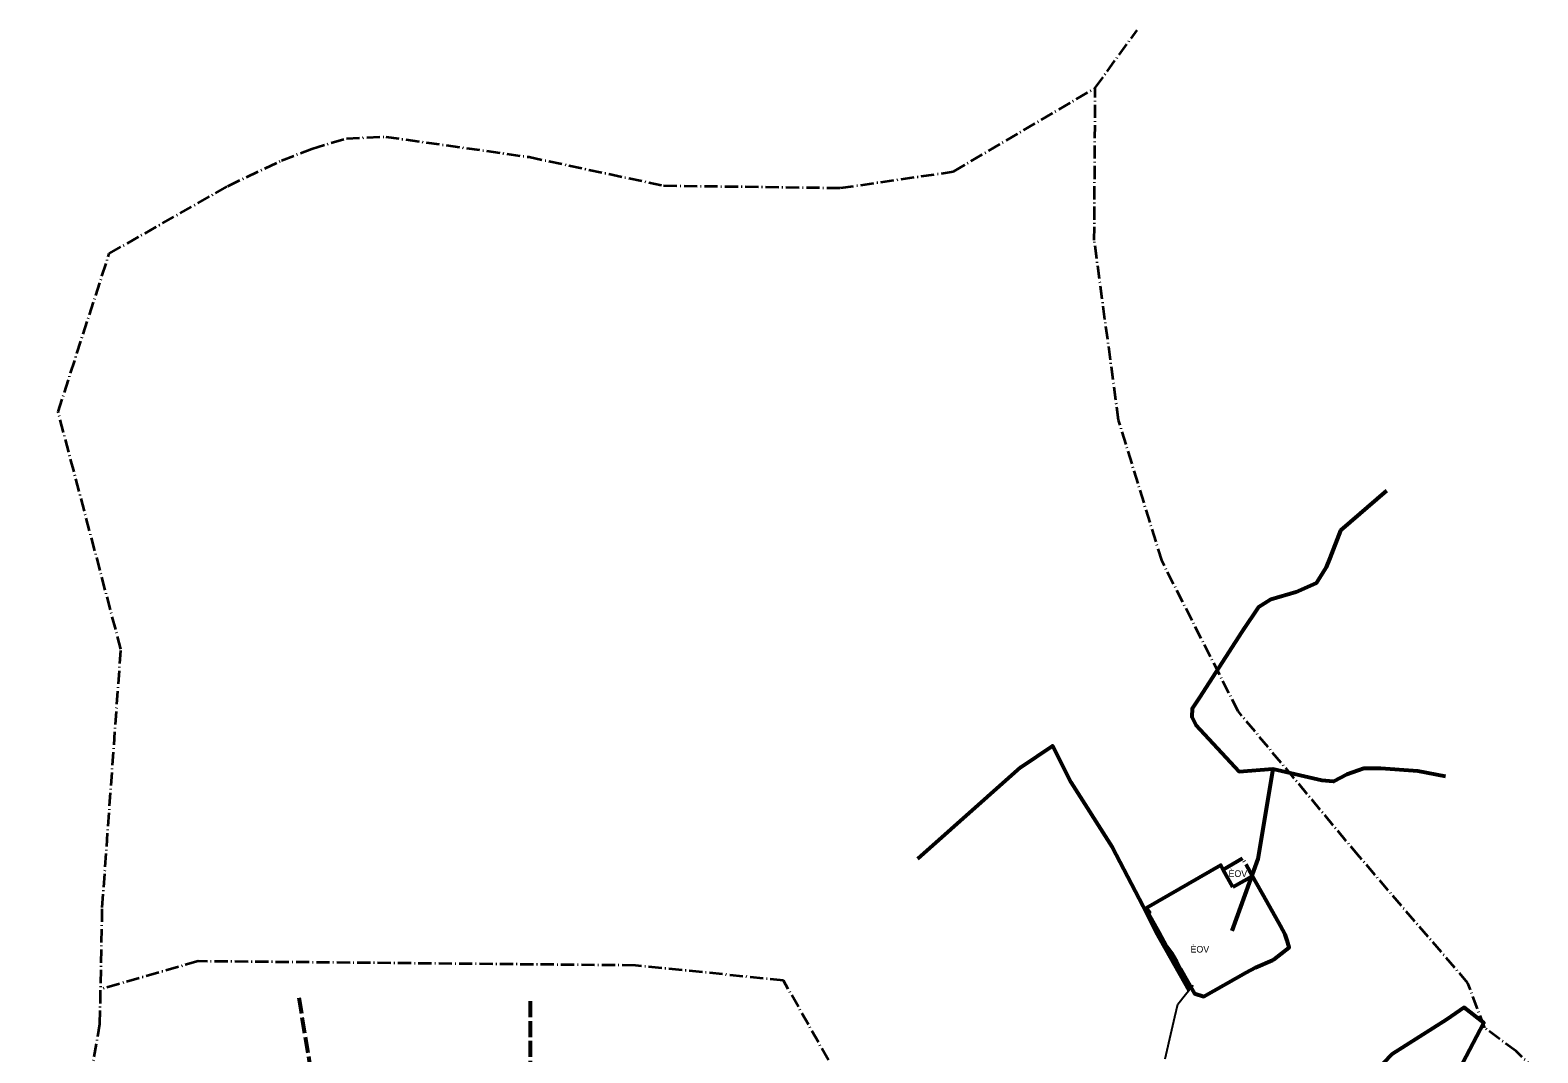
# Model space of a CAD drawing. Extents: x -650270 to -643402, y -1075206 to -1066724.
# Drawn here: x -647793 to -645515, y -1069326 to -1067780 of the extents above; entities that cross this region are included whole.
import ezdxf

# ---------------------------------------------------------------- set-up
doc = ezdxf.new("R2010")
doc.units = 0
doc.header["$LTSCALE"] = 4
doc.linetypes.add('DOT_DASHED', pattern=[7.7, 5, -1.2, 0.3, -1.2])
doc.linetypes.add('LONG_DASHED', pattern=[7.5, 6, -1.5])
for name, color, linetype, lineweight in [('16', 7, 'Continuous', 25), ('17', 7, 'DOT_DASHED', 35), ('21', 7, 'Continuous', 53), ('22', 7, 'DOT_DASHED', 53), ('43', 7, 'Continuous', 53), ('47', 7, 'Continuous', 40), ('48', 7, 'Continuous', 53), ('50', 7, 'Continuous', 53)]:
    doc.layers.add(name, color=color, linetype=linetype, lineweight=lineweight)

msp = doc.modelspace()

# ---------------------------------------------------------------- linework, layer by layer
at = {"layer": '16'}
msp.add_lwpolyline([(-646077.688, -1069335.173), (-646067.55, -1069291.329), (-646062.988, -1069271.856), (-646058.427, -1069252.383), (-646047.044, -1069237.982), (-646035.66, -1069223.58)], dxfattribs=at)
at = {"layer": '17'}
for points in [[(-648163.245, -1069677.659), (-647956.36, -1069616.266), (-647792.66, -1069528.568), (-647711.796, -1069423.024), (-647687.185, -1069282.298), (-647683.669, -1069106.39), (-647655.542, -1068715.876), (-647750.47, -1068357.024), (-647673.122, -1068117.79), (-647493.814, -1068015.764), (-647412.95, -1067977.064), (-647367.244, -1067959.473), (-647314.919, -1067943.73), (-647255.446, -1067941.26), (-647038.873, -1067971.862), (-646835.475, -1068015.092), (-646568.272, -1068018.608), (-646397.754, -1067993.997), (-646183.288, -1067867.427), (-646120.196, -1067780.102)], [(-644568.435, -1070960.552), (-644606.234, -1070747.935), (-644654.246, -1070597.895), (-644792.283, -1070387.84), (-645046.599, -1070192.79), (-645228.623, -1070004.752), (-645232.28, -1069980.924), (-645262.713, -1069836.388), (-645315.002, -1069657.333), (-645409.031, -1069473.75), (-645471.738, -1069397.026), (-645547.224, -1069323.801), (-645594.94, -1069288.511), (-645620.197, -1069220.915), (-645784.301, -1069029.743), (-645967.439, -1068809.81), (-646082.481, -1068583.109), (-646148.037, -1068369.943), (-646184.835, -1068097.563), (-646183.288, -1067867.427)], [(-646584.549, -1071124.89), (-646410.298, -1070907.26), (-646232.358, -1070648.654), (-646054.418, -1070451.734), (-646014.085, -1070223.971), (-646011.713, -1070105.345), (-646127.967, -1070010.443), (-646431.058, -1069900.12), (-646583.457, -1069759.191), (-646548.91, -1069578.56), (-646571.479, -1069363.822), (-646654.434, -1069216.7), (-646878.202, -1069194.008), (-647539.001, -1069187.705), (-647686.136, -1069229.838)]]:
    msp.add_lwpolyline(points, dxfattribs=at)
at = {"layer": '21'}
msp.add_lwpolyline([(-645975.48, -1069075.71), (-645990.13, -1069049.301), (-645993.848, -1069042.589), (-646106.311, -1069107.251), (-646101.57, -1069113.74), (-646103.591, -1069114.91), (-646087.52, -1069143.7), (-646075.88, -1069165.21), (-646067.71, -1069176.01), (-646060.75, -1069188.02), (-646054.873, -1069199.282), (-646054.678, -1069199.2), (-646042, -1069221.33), (-646033.271, -1069236.507), (-646019.24, -1069241.19), (-645955.1, -1069204.88), (-645941.385, -1069197.185), (-645915.71, -1069186.03), (-645913.47, -1069185.07), (-645890.317, -1069166.97), (-645893.49, -1069156.53), (-645896.35, -1069147.12), (-645903.35, -1069134.27), (-645924.02, -1069097.485), (-645945.685, -1069058.929)], close=True, dxfattribs=at)
at = {"layer": '22'}
msp.add_lwpolyline([(-645945.685, -1069058.929), (-645960.67, -1069032.26), (-645975.4, -1069040.78), (-645990.13, -1069049.3)], dxfattribs=at)
at = {"layer": '43', "linetype": 'LONG_DASHED'}
for p, q in [((-647386.783, -1069243.021), (-647337.628, -1069543.417)), ((-647037.18, -1069248.217), (-647037.18, -1069545.391))]:
    msp.add_line(p, q, dxfattribs=at)
at = {"layer": '48'}
for points in [[(-646451.322, -1069032.874), (-646295.932, -1068894.5), (-646248.016, -1068862.258), (-646220.085, -1068916.892), (-646157.557, -1069015.41), (-646111.432, -1069104.078), (-646092.013, -1069143.037), (-646041.918, -1069231.497)], [(-645552.068, -1069638.526), (-645642.407, -1069592.458), (-645649.87, -1069590.965), (-645728.088, -1069578.714), (-645803.181, -1069570.441), (-645810.478, -1069572.033), (-645787.737, -1069536.624), (-645752.519, -1069500.102), (-645720.378, -1069461.316), (-645684.581, -1069417.092), (-645648.533, -1069373.739), (-645628.035, -1069340.99), (-645596.435, -1069280.712), (-645626.154, -1069257.704), (-645652.038, -1069275.918)], [(-645652.038, -1069275.918), (-645734.927, -1069328.215), (-645842.55, -1069439.942), (-645883.788, -1069480.205), (-645886.806, -1069494.297), (-645927.806, -1069503.664)]]:
    msp.add_lwpolyline(points, dxfattribs=at)
at = {"layer": '50'}
msp.add_line((-645841.148, -1068914.276), (-645915.285, -1068897.386), dxfattribs=at)
for points in [[(-645743.059, -1068476.379), (-645812.854, -1068536.591), (-645828.899, -1068578.338), (-645834.514, -1068591.986), (-645849.757, -1068616.071), (-645880.242, -1068629.719), (-645917.947, -1068640.958), (-645937.201, -1068653.001), (-645959.664, -1068686.72)], [(-645957.124, -1068682.702), (-646025.934, -1068788.829), (-646037.089, -1068805.562), (-646037.554, -1068818.111), (-646031.512, -1068830.196), (-645965.745, -1068900.792), (-645915.165, -1068896.655)], [(-645915.285, -1068897.386), (-645937.63, -1069033.023), (-645976.999, -1069141.866)], [(-645654.382, -1068908.587), (-645695.934, -1068900.379), (-645752.035, -1068896.262), (-645777.633, -1068896.262), (-645803.3, -1068905.491), (-645823.286, -1068915.717), (-645841.148, -1068914.276)]]:
    msp.add_lwpolyline(points, dxfattribs=at)

# ---------------------------------------------------------------- texts
at = {"layer": '47'}
for p in [(-645982.021, -1069060.206), (-646039.435, -1069174.524)]:
    msp.add_text('ÈOV', height=10, dxfattribs=at).set_placement(p)

doc.saveas('drawing.dxf')
